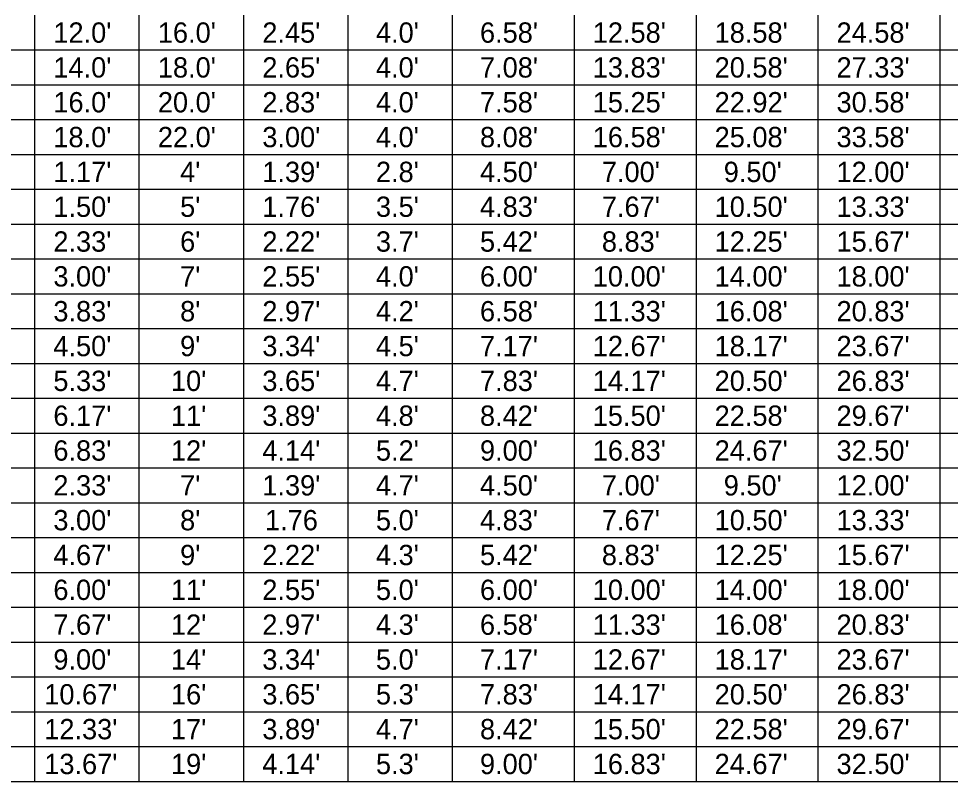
# Model space of a CAD drawing. Extents: x 1.7 to 14.4, y 0 to 7.8.
# Drawn here: x 4.886 to 8.096, y 2.49 to 5.118 of the extents above; entities that cross this region are included whole.
import ezdxf

# ---------------------------------------------------------------- set-up
doc = ezdxf.new("R2010")
doc.units = 0
doc.layers.add('Table', color=7, linetype='Continuous')

msp = doc.modelspace()

# ---------------------------------------------------------------- linework, layer by layer
at = {"layer": 'Table'}
for points in [[(4.94, 5.13), (4.94, 5.01), (4.94, 4.89), (4.94, 4.77), (4.94, 4.65), (4.94, 4.53), (4.94, 4.41), (4.94, 4.29), (4.94, 4.17), (4.94, 4.05), (4.94, 3.93), (4.94, 3.81), (4.94, 3.69), (4.94, 3.57), (4.94, 3.45), (4.94, 3.33), (4.94, 3.21), (4.94, 3.09), (4.94, 2.97), (4.94, 2.85), (4.94, 2.73), (4.94, 2.61), (4.94, 2.49)], [(5.3, 5.13), (5.3, 5.01), (5.3, 4.89), (5.3, 4.77), (5.3, 4.65), (5.3, 4.53), (5.3, 4.41), (5.3, 4.29), (5.3, 4.17), (5.3, 4.05), (5.3, 3.93), (5.3, 3.81), (5.3, 3.69), (5.3, 3.57), (5.3, 3.45), (5.3, 3.33), (5.3, 3.21), (5.3, 3.09), (5.3, 2.97), (5.3, 2.85), (5.3, 2.73), (5.3, 2.61), (5.3, 2.49)], [(5.66, 5.13), (5.66, 5.01), (5.66, 4.89), (5.66, 4.77), (5.66, 4.65), (5.66, 4.53), (5.66, 4.41), (5.66, 4.29), (5.66, 4.17), (5.66, 4.05), (5.66, 3.93), (5.66, 3.81), (5.66, 3.69), (5.66, 3.57), (5.66, 3.45), (5.66, 3.33), (5.66, 3.21), (5.66, 3.09), (5.66, 2.97), (5.66, 2.85), (5.66, 2.73), (5.66, 2.61), (5.66, 2.49)], [(6.02, 5.13), (6.02, 5.01), (6.02, 4.89), (6.02, 4.77), (6.02, 4.65), (6.02, 4.53), (6.02, 4.41), (6.02, 4.29), (6.02, 4.17), (6.02, 4.05), (6.02, 3.93), (6.02, 3.81), (6.02, 3.69), (6.02, 3.57), (6.02, 3.45), (6.02, 3.33), (6.02, 3.21), (6.02, 3.09), (6.02, 2.97), (6.02, 2.85), (6.02, 2.73), (6.02, 2.61), (6.02, 2.49)], [(6.38, 5.13), (6.38, 5.01), (6.38, 4.89), (6.38, 4.77), (6.38, 4.65), (6.38, 4.53), (6.38, 4.41), (6.38, 4.29), (6.38, 4.17), (6.38, 4.05), (6.38, 3.93), (6.38, 3.81), (6.38, 3.69), (6.38, 3.57), (6.38, 3.45), (6.38, 3.33), (6.38, 3.21), (6.38, 3.09), (6.38, 2.97), (6.38, 2.85), (6.38, 2.73), (6.38, 2.61), (6.38, 2.49)], [(6.8, 5.13), (6.8, 5.01), (6.8, 4.89), (6.8, 4.77), (6.8, 4.65), (6.8, 4.53), (6.8, 4.41), (6.8, 4.29), (6.8, 4.17), (6.8, 4.05), (6.8, 3.93), (6.8, 3.81), (6.8, 3.69), (6.8, 3.57), (6.8, 3.45), (6.8, 3.33), (6.8, 3.21), (6.8, 3.09), (6.8, 2.97), (6.8, 2.85), (6.8, 2.73), (6.8, 2.61), (6.8, 2.49)], [(7.22, 5.13), (7.22, 5.01), (7.22, 4.89), (7.22, 4.77), (7.22, 4.65), (7.22, 4.53), (7.22, 4.41), (7.22, 4.29), (7.22, 4.17), (7.22, 4.05), (7.22, 3.93), (7.22, 3.81), (7.22, 3.69), (7.22, 3.57), (7.22, 3.45), (7.22, 3.33), (7.22, 3.21), (7.22, 3.09), (7.22, 2.97), (7.22, 2.85), (7.22, 2.73), (7.22, 2.61), (7.22, 2.49)], [(7.64, 5.13), (7.64, 5.01), (7.64, 4.89), (7.64, 4.77), (7.64, 4.65), (7.64, 4.53), (7.64, 4.41), (7.64, 4.29), (7.64, 4.17), (7.64, 4.05), (7.64, 3.93), (7.64, 3.81), (7.64, 3.69), (7.64, 3.57), (7.64, 3.45), (7.64, 3.33), (7.64, 3.21), (7.64, 3.09), (7.64, 2.97), (7.64, 2.85), (7.64, 2.73), (7.64, 2.61), (7.64, 2.49)], [(8.06, 5.13), (8.06, 5.01), (8.06, 4.89), (8.06, 4.77), (8.06, 4.65), (8.06, 4.53), (8.06, 4.41), (8.06, 4.29), (8.06, 4.17), (8.06, 4.05), (8.06, 3.93), (8.06, 3.81), (8.06, 3.69), (8.06, 3.57), (8.06, 3.45), (8.06, 3.33), (8.06, 3.21), (8.06, 3.09), (8.06, 2.97), (8.06, 2.85), (8.06, 2.73), (8.06, 2.61), (8.06, 2.49)], [(2.3, 5.01), (2.6, 5.01), (2.9, 5.01), (3.2, 5.01), (3.62, 5.01), (4.04, 5.01), (4.52, 5.01), (4.94, 5.01), (5.3, 5.01), (5.66, 5.01), (6.02, 5.01), (6.38, 5.01), (6.8, 5.01), (7.22, 5.01), (7.64, 5.01), (8.06, 5.01), (8.42, 5.01)], [(2.3, 4.89), (2.6, 4.89), (2.9, 4.89), (3.2, 4.89), (3.62, 4.89), (4.04, 4.89), (4.52, 4.89), (4.94, 4.89), (5.3, 4.89), (5.66, 4.89), (6.02, 4.89), (6.38, 4.89), (6.8, 4.89), (7.22, 4.89), (7.64, 4.89), (8.06, 4.89), (8.42, 4.89)], [(2.3, 4.77), (2.6, 4.77), (2.9, 4.77), (3.2, 4.77), (3.62, 4.77), (4.04, 4.77), (4.52, 4.77), (4.94, 4.77), (5.3, 4.77), (5.66, 4.77), (6.02, 4.77), (6.38, 4.77), (6.8, 4.77), (7.22, 4.77), (7.64, 4.77), (8.06, 4.77), (8.42, 4.77)], [(1.7, 4.65), (1.94, 4.65), (2.3, 4.65), (2.6, 4.65), (2.9, 4.65), (3.2, 4.65), (3.62, 4.65), (4.04, 4.65), (4.52, 4.65), (4.94, 4.65), (5.3, 4.65), (5.66, 4.65), (6.02, 4.65), (6.38, 4.65), (6.8, 4.65), (7.22, 4.65), (7.64, 4.65), (8.06, 4.65), (8.42, 4.65)], [(2.3, 4.53), (2.6, 4.53), (2.9, 4.53), (3.2, 4.53), (3.62, 4.53), (4.04, 4.53), (4.52, 4.53), (4.94, 4.53), (5.3, 4.53), (5.66, 4.53), (6.02, 4.53), (6.38, 4.53), (6.8, 4.53), (7.22, 4.53), (7.64, 4.53), (8.06, 4.53), (8.42, 4.53)], [(2.3, 4.41), (2.6, 4.41), (2.9, 4.41), (3.2, 4.41), (3.62, 4.41), (4.04, 4.41), (4.52, 4.41), (4.94, 4.41), (5.3, 4.41), (5.66, 4.41), (6.02, 4.41), (6.38, 4.41), (6.8, 4.41), (7.22, 4.41), (7.64, 4.41), (8.06, 4.41), (8.42, 4.41)], [(2.3, 4.29), (2.6, 4.29), (2.9, 4.29), (3.2, 4.29), (3.62, 4.29), (4.04, 4.29), (4.52, 4.29), (4.94, 4.29), (5.3, 4.29), (5.66, 4.29), (6.02, 4.29), (6.38, 4.29), (6.8, 4.29), (7.22, 4.29), (7.64, 4.29), (8.06, 4.29), (8.42, 4.29)], [(2.3, 4.17), (2.6, 4.17), (2.9, 4.17), (3.2, 4.17), (3.62, 4.17), (4.04, 4.17), (4.52, 4.17), (4.94, 4.17), (5.3, 4.17), (5.66, 4.17), (6.02, 4.17), (6.38, 4.17), (6.8, 4.17), (7.22, 4.17), (7.64, 4.17), (8.06, 4.17), (8.42, 4.17)], [(2.3, 4.05), (2.6, 4.05), (2.9, 4.05), (3.2, 4.05), (3.62, 4.05), (4.04, 4.05), (4.52, 4.05), (4.94, 4.05), (5.3, 4.05), (5.66, 4.05), (6.02, 4.05), (6.38, 4.05), (6.8, 4.05), (7.22, 4.05), (7.64, 4.05), (8.06, 4.05), (8.42, 4.05)], [(2.3, 3.93), (2.6, 3.93), (2.9, 3.93), (3.2, 3.93), (3.62, 3.93), (4.04, 3.93), (4.52, 3.93), (4.94, 3.93), (5.3, 3.93), (5.66, 3.93), (6.02, 3.93), (6.38, 3.93), (6.8, 3.93), (7.22, 3.93), (7.64, 3.93), (8.06, 3.93), (8.42, 3.93)], [(2.3, 3.81), (2.6, 3.81), (2.9, 3.81), (3.2, 3.81), (3.62, 3.81), (4.04, 3.81), (4.52, 3.81), (4.94, 3.81), (5.3, 3.81), (5.66, 3.81), (6.02, 3.81), (6.38, 3.81), (6.8, 3.81), (7.22, 3.81), (7.64, 3.81), (8.06, 3.81), (8.42, 3.81)], [(2.3, 3.69), (2.6, 3.69), (2.9, 3.69), (3.2, 3.69), (3.62, 3.69), (4.04, 3.69), (4.52, 3.69), (4.94, 3.69), (5.3, 3.69), (5.66, 3.69), (6.02, 3.69), (6.38, 3.69), (6.8, 3.69), (7.22, 3.69), (7.64, 3.69), (8.06, 3.69), (8.42, 3.69)], [(1.94, 3.57), (2.3, 3.57), (2.6, 3.57), (2.9, 3.57), (3.2, 3.57), (3.62, 3.57), (4.04, 3.57), (4.52, 3.57), (4.94, 3.57), (5.3, 3.57), (5.66, 3.57), (6.02, 3.57), (6.38, 3.57), (6.8, 3.57), (7.22, 3.57), (7.64, 3.57), (8.06, 3.57), (8.42, 3.57)], [(2.3, 3.45), (2.6, 3.45), (2.9, 3.45), (3.2, 3.45), (3.62, 3.45), (4.04, 3.45), (4.52, 3.45), (4.94, 3.45), (5.3, 3.45), (5.66, 3.45), (6.02, 3.45), (6.38, 3.45), (6.8, 3.45), (7.22, 3.45), (7.64, 3.45), (8.06, 3.45), (8.42, 3.45)], [(2.3, 3.33), (2.6, 3.33), (2.9, 3.33), (3.2, 3.33), (3.62, 3.33), (4.04, 3.33), (4.52, 3.33), (4.94, 3.33), (5.3, 3.33), (5.66, 3.33), (6.02, 3.33), (6.38, 3.33), (6.8, 3.33), (7.22, 3.33), (7.64, 3.33), (8.06, 3.33), (8.42, 3.33)], [(2.3, 3.21), (2.6, 3.21), (2.9, 3.21), (3.2, 3.21), (3.62, 3.21), (4.04, 3.21), (4.52, 3.21), (4.94, 3.21), (5.3, 3.21), (5.66, 3.21), (6.02, 3.21), (6.38, 3.21), (6.8, 3.21), (7.22, 3.21), (7.64, 3.21), (8.06, 3.21), (8.42, 3.21)], [(2.3, 3.09), (2.6, 3.09), (2.9, 3.09), (3.2, 3.09), (3.62, 3.09), (4.04, 3.09), (4.52, 3.09), (4.94, 3.09), (5.3, 3.09), (5.66, 3.09), (6.02, 3.09), (6.38, 3.09), (6.8, 3.09), (7.22, 3.09), (7.64, 3.09), (8.06, 3.09), (8.42, 3.09)], [(2.3, 2.97), (2.6, 2.97), (2.9, 2.97), (3.2, 2.97), (3.62, 2.97), (4.04, 2.97), (4.52, 2.97), (4.94, 2.97), (5.3, 2.97), (5.66, 2.97), (6.02, 2.97), (6.38, 2.97), (6.8, 2.97), (7.22, 2.97), (7.64, 2.97), (8.06, 2.97), (8.42, 2.97)], [(2.3, 2.85), (2.6, 2.85), (2.9, 2.85), (3.2, 2.85), (3.62, 2.85), (4.04, 2.85), (4.52, 2.85), (4.94, 2.85), (5.3, 2.85), (5.66, 2.85), (6.02, 2.85), (6.38, 2.85), (6.8, 2.85), (7.22, 2.85), (7.64, 2.85), (8.06, 2.85), (8.42, 2.85)], [(2.3, 2.73), (2.6, 2.73), (2.9, 2.73), (3.2, 2.73), (3.62, 2.73), (4.04, 2.73), (4.52, 2.73), (4.94, 2.73), (5.3, 2.73), (5.66, 2.73), (6.02, 2.73), (6.38, 2.73), (6.8, 2.73), (7.22, 2.73), (7.64, 2.73), (8.06, 2.73), (8.42, 2.73)], [(2.3, 2.61), (2.6, 2.61), (2.9, 2.61), (3.2, 2.61), (3.62, 2.61), (4.04, 2.61), (4.52, 2.61), (4.94, 2.61), (5.3, 2.61), (5.66, 2.61), (6.02, 2.61), (6.38, 2.61), (6.8, 2.61), (7.22, 2.61), (7.64, 2.61), (8.06, 2.61), (8.42, 2.61)], [(1.7, 2.49), (1.94, 2.49), (2.3, 2.49), (2.6, 2.49), (2.9, 2.49), (3.2, 2.49), (3.62, 2.49), (4.04, 2.49), (4.52, 2.49), (4.94, 2.49), (5.3, 2.49), (5.66, 2.49), (6.02, 2.49), (6.38, 2.49), (6.8, 2.49), (7.22, 2.49), (7.64, 2.49), (8.06, 2.49), (8.42, 2.49)]]:
    msp.add_lwpolyline(points, dxfattribs=at)

# ---------------------------------------------------------------- texts
for s, p in [("12.0'", (5.0054, 5.035)), ("16.0'", (5.3654, 5.035)), ("2.45'", (5.7254, 5.035)), ("4.0'", (6.1169, 5.035)), ("6.58'", (6.4754, 5.035)), ("12.58'", (6.864, 5.035)), ("18.58'", (7.284, 5.035)), ("24.58'", (7.704, 5.035)), ("14.0'", (5.0054, 4.915)), ("18.0'", (5.3654, 4.915)), ("2.65'", (5.7254, 4.915)), ("4.0'", (6.1169, 4.915)), ("7.08'", (6.4754, 4.915)), ("13.83'", (6.864, 4.915)), ("20.58'", (7.284, 4.915)), ("27.33'", (7.704, 4.915)), ("16.0'", (5.0054, 4.795)), ("20.0'", (5.3654, 4.795)), ("2.83'", (5.7254, 4.795)), ("4.0'", (6.1169, 4.795)), ("7.58'", (6.4754, 4.795)), ("15.25'", (6.864, 4.795)), ("22.92'", (7.284, 4.795)), ("30.58'", (7.704, 4.795)), ("18.0'", (5.0054, 4.675)), ("22.0'", (5.3654, 4.675)), ("3.00'", (5.7254, 4.675)), ("4.0'", (6.1169, 4.675)), ("8.08'", (6.4754, 4.675)), ("16.58'", (6.864, 4.675)), ("25.08'", (7.284, 4.675)), ("33.58'", (7.704, 4.675)), ("1.17'", (5.0054, 4.555)), ("4'", (5.4421, 4.555)), ("1.39'", (5.7254, 4.555)), ("2.8'", (6.1169, 4.555)), ("4.50'", (6.4754, 4.555)), ("7.00'", (6.8954, 4.555)), ("9.50'", (7.3154, 4.555)), ("12.00'", (7.704, 4.555)), ("1.50'", (5.0054, 4.435)), ("5'", (5.4421, 4.435)), ("1.76'", (5.7254, 4.435)), ("3.5'", (6.1169, 4.435)), ("4.83'", (6.4754, 4.435)), ("7.67'", (6.8954, 4.435)), ("10.50'", (7.284, 4.435)), ("13.33'", (7.704, 4.435)), ("2.33'", (5.0054, 4.315)), ("6'", (5.4421, 4.315)), ("2.22'", (5.7254, 4.315)), ("3.7'", (6.1169, 4.315)), ("5.42'", (6.4754, 4.315)), ("8.83'", (6.8954, 4.315)), ("12.25'", (7.284, 4.315)), ("15.67'", (7.704, 4.315)), ("3.00'", (5.0054, 4.195)), ("7'", (5.4421, 4.195)), ("2.55'", (5.7254, 4.195)), ("4.0'", (6.1169, 4.195)), ("6.00'", (6.4754, 4.195)), ("10.00'", (6.864, 4.195)), ("14.00'", (7.284, 4.195)), ("18.00'", (7.704, 4.195)), ("3.83'", (5.0054, 4.075)), ("8'", (5.4421, 4.075)), ("2.97'", (5.7254, 4.075)), ("4.2'", (6.1169, 4.075)), ("6.58'", (6.4754, 4.075)), ("11.33'", (6.864, 4.075)), ("16.08'", (7.284, 4.075)), ("20.83'", (7.704, 4.075)), ("4.50'", (5.0054, 3.955)), ("9'", (5.4421, 3.955)), ("3.34'", (5.7254, 3.955)), ("4.5'", (6.1169, 3.955)), ("7.17'", (6.4754, 3.955)), ("12.67'", (6.864, 3.955)), ("18.17'", (7.284, 3.955)), ("23.67'", (7.704, 3.955)), ("5.33'", (5.0054, 3.835)), ("10'", (5.4106, 3.835)), ("3.65'", (5.7254, 3.835)), ("4.7'", (6.1169, 3.835)), ("7.83'", (6.4754, 3.835)), ("14.17'", (6.864, 3.835)), ("20.50'", (7.284, 3.835)), ("26.83'", (7.704, 3.835)), ("6.17'", (5.0054, 3.715)), ("11'", (5.4106, 3.715)), ("3.89'", (5.7254, 3.715)), ("4.8'", (6.1169, 3.715)), ("8.42'", (6.4754, 3.715)), ("15.50'", (6.864, 3.715)), ("22.58'", (7.284, 3.715)), ("29.67'", (7.704, 3.715)), ("6.83'", (5.0054, 3.595)), ("12'", (5.4106, 3.595)), ("4.14'", (5.7254, 3.595)), ("5.2'", (6.1169, 3.595)), ("9.00'", (6.4754, 3.595)), ("16.83'", (6.864, 3.595)), ("24.67'", (7.284, 3.595)), ("32.50'", (7.704, 3.595)), ("2.33'", (5.0054, 3.475)), ("7'", (5.4421, 3.475)), ("1.39'", (5.7254, 3.475)), ("4.7'", (6.1169, 3.475)), ("4.50'", (6.4754, 3.475)), ("7.00'", (6.8954, 3.475)), ("9.50'", (7.3154, 3.475)), ("12.00'", (7.704, 3.475)), ("3.00'", (5.0054, 3.355)), ("8'", (5.4421, 3.355)), ('1.76', (5.7347, 3.355)), ("5.0'", (6.1169, 3.355)), ("4.83'", (6.4754, 3.355)), ("7.67'", (6.8954, 3.355)), ("10.50'", (7.284, 3.355)), ("13.33'", (7.704, 3.355)), ("4.67'", (5.0054, 3.235)), ("9'", (5.4421, 3.235)), ("2.22'", (5.7254, 3.235)), ("4.3'", (6.1169, 3.235)), ("5.42'", (6.4754, 3.235)), ("8.83'", (6.8954, 3.235)), ("12.25'", (7.284, 3.235)), ("15.67'", (7.704, 3.235)), ("6.00'", (5.0054, 3.115)), ("11'", (5.4106, 3.115)), ("2.55'", (5.7254, 3.115)), ("5.0'", (6.1169, 3.115)), ("6.00'", (6.4754, 3.115)), ("10.00'", (6.864, 3.115)), ("14.00'", (7.284, 3.115)), ("18.00'", (7.704, 3.115)), ("7.67'", (5.0054, 2.995)), ("12'", (5.4106, 2.995)), ("2.97'", (5.7254, 2.995)), ("4.3'", (6.1169, 2.995)), ("6.58'", (6.4754, 2.995)), ("11.33'", (6.864, 2.995)), ("16.08'", (7.284, 2.995)), ("20.83'", (7.704, 2.995)), ("9.00'", (5.0054, 2.875)), ("14'", (5.4106, 2.875)), ("3.34'", (5.7254, 2.875)), ("5.0'", (6.1169, 2.875)), ("7.17'", (6.4754, 2.875)), ("12.67'", (6.864, 2.875)), ("18.17'", (7.284, 2.875)), ("23.67'", (7.704, 2.875)), ("10.67'", (4.974, 2.755)), ("16'", (5.4106, 2.755)), ("3.65'", (5.7254, 2.755)), ("5.3'", (6.1169, 2.755)), ("7.83'", (6.4754, 2.755)), ("20.50'", (7.284, 2.755)), ("26.83'", (7.704, 2.755)), ("14.17'", (6.864, 2.755)), ("12.33'", (4.974, 2.635)), ("17'", (5.4106, 2.635)), ("3.89'", (5.7254, 2.635)), ("4.7'", (6.1169, 2.635)), ("8.42'", (6.4754, 2.635)), ("15.50'", (6.864, 2.635)), ("22.58'", (7.284, 2.635)), ("29.67'", (7.704, 2.635)), ("13.67'", (4.974, 2.515)), ("19'", (5.4106, 2.515)), ("4.14'", (5.7254, 2.515)), ("5.3'", (6.1169, 2.515)), ("9.00'", (6.4754, 2.515)), ("16.83'", (6.864, 2.515)), ("24.67'", (7.284, 2.515)), ("32.50'", (7.704, 2.515))]:
    msp.add_text(s, height=0.07, rotation=0, dxfattribs=at).set_placement(p)

doc.saveas('drawing.dxf')
